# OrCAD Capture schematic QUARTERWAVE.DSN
size A
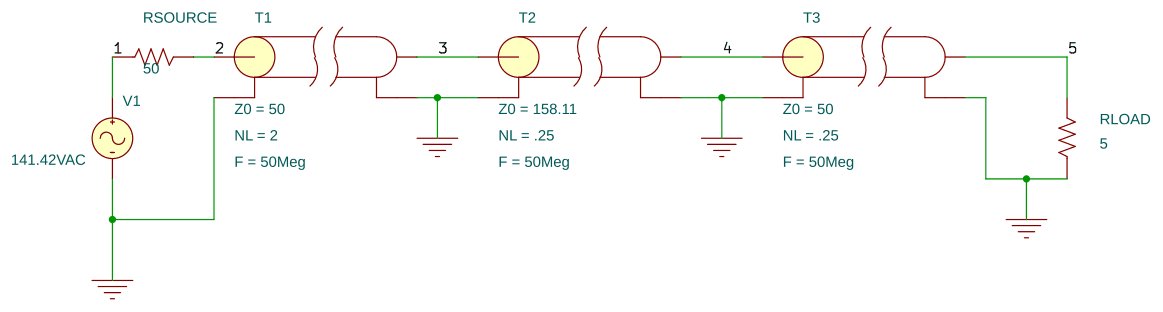
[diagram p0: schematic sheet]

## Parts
RLOAD  5  [AX/RC05]
RSOURCE  50  [AX/RC05]
T1  T
T2  T
T3  T
V1  VAC

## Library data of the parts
RLOAD RSOURCE = R
T1 = T: F: 50Meg; NL: 2; Z0: 50
T2 = T: F: 50Meg; NL: .25; Z0: 158.11
T3 = T: F: 50Meg; NL: .25; Z0: 50
V1 = VAC: ACMAG: 141.42VAC

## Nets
0: RLOAD.1 T1.2(A-) T1.4(B-) T2.2(A-) T2.4(B-) T3.2(A-) T3.4(B-) V1.2(-)
1: RSOURCE.1 V1.1(+)
2: RSOURCE.2 T1.1(A+)
3: T1.3(B+) T2.1(A+)
4: T2.3(B+) T3.1(A+)
5: RLOAD.2 T3.3(B+)
